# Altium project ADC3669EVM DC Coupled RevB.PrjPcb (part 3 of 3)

## Sheet FTDI USB Input.SchDoc: FTDI USB
size 431 x 279 mm; Date: Not shown in title block; ApprovedBy: Not shown in title block; CheckedBy: Not shown in title block; Author: Not shown in title block; CompanyName: Not shown in title block; Engineer: Not shown in title block; Organization: Not shown in title block; Address1: Not shown in title block; Address2: Not shown in title block; Address3: Not shown in title block; Address4: Not shown in title block; DocumentNumber: 1; Revision: Use project parameter SCH_Rev; SheetNumber: 13; SheetTotal: 17; PageSetup: Record=PageOptions¦CenterHorizontal=True¦CenterVertical=True¦PrintScale=1.00¦XCorrection=1.00¦YCorrection=1.00¦PrintKind=0¦BorderSize=5000000¦LeftOffset=0¦BottomOffset=0¦Orientation=2¦PaperLength=1000¦PaperWidth=1000¦Scale=100¦PaperSource=15¦PrintQuality=600¦MediaType=1¦DitherType=10¦PaperKind=Letter¦PrintScaleMode=1
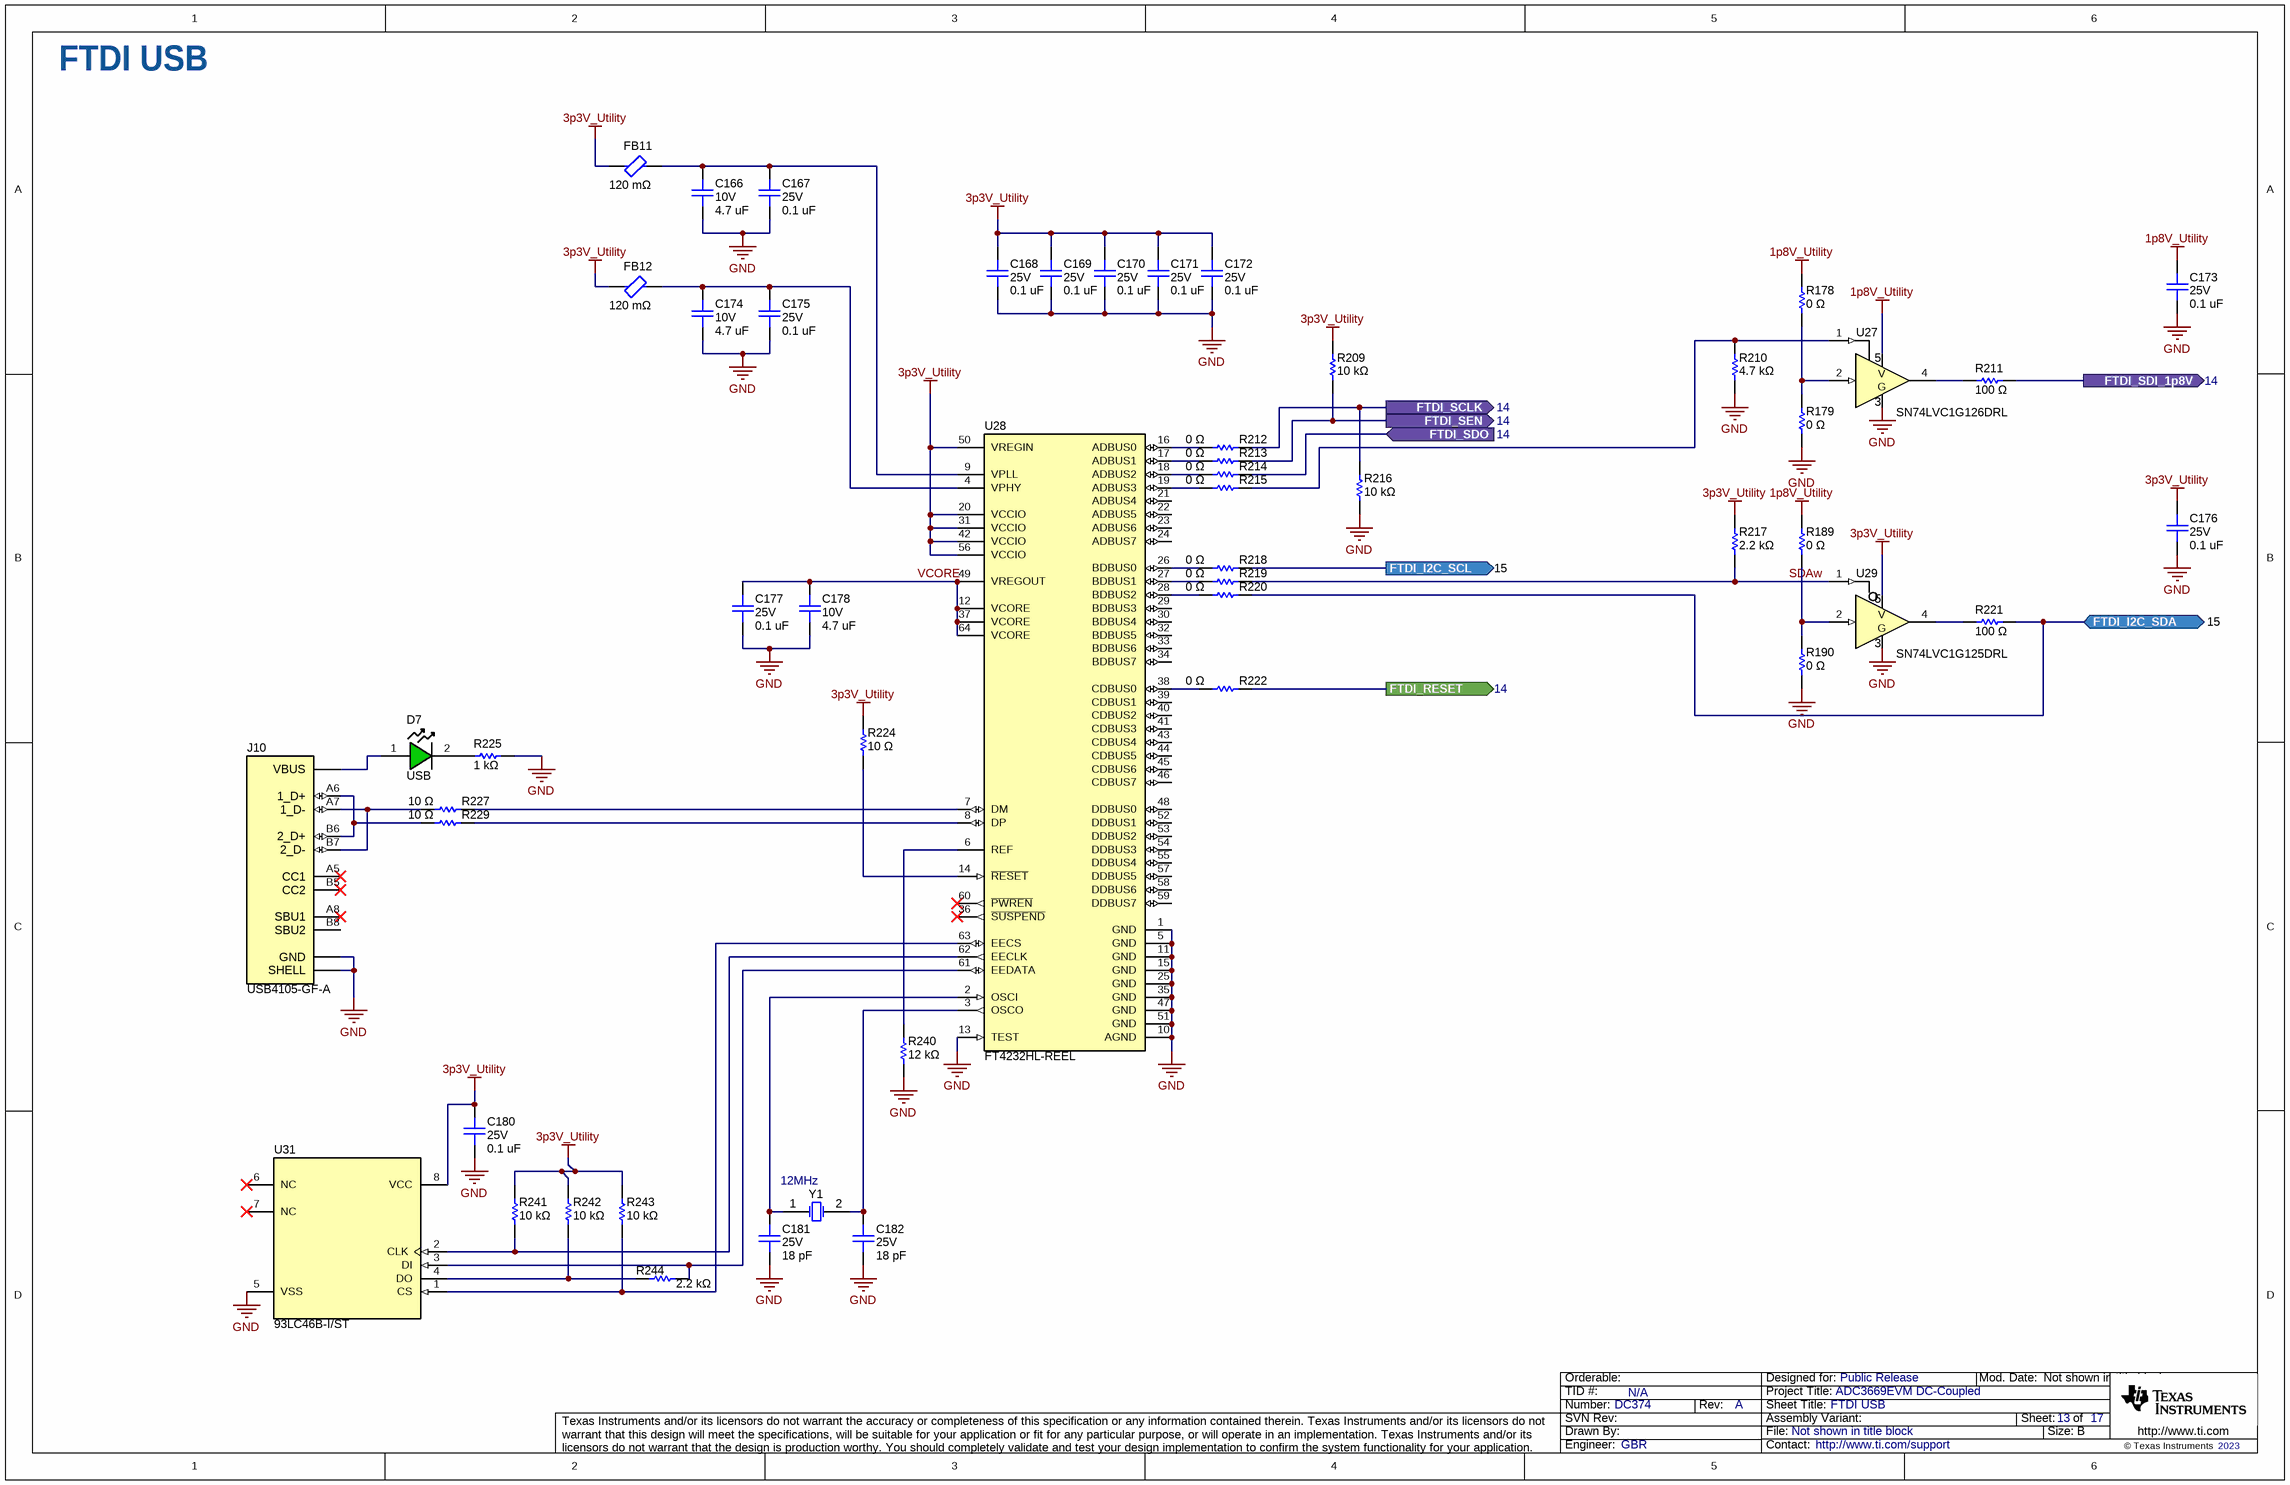
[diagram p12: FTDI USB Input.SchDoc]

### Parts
C166  value 4.7 uF  Voltage - Rated: 10V  [0402L_cap]  (hidden comment: C1005X5R1A475K050BE)
C167  value 0.1 uF  Voltage - Rated: 25V  [0402L_cap]  (hidden comment: C1005X5R1E104K050BC)
C168  value 0.1 uF  Voltage - Rated: 25V  [0402L_cap]  (hidden comment: C1005X5R1E104K050BC)
C169  value 0.1 uF  Voltage - Rated: 25V  [0402L_cap]  (hidden comment: C1005X5R1E104K050BC)
C170  value 0.1 uF  Voltage - Rated: 25V  [0402L_cap]  (hidden comment: C1005X5R1E104K050BC)
C171  value 0.1 uF  Voltage - Rated: 25V  [0402L_cap]  (hidden comment: C1005X5R1E104K050BC)
C172  value 0.1 uF  Voltage - Rated: 25V  [0402L_cap]  (hidden comment: C1005X5R1E104K050BC)
C173  value 0.1 uF  Voltage - Rated: 25V  [0402L_cap]  (hidden comment: C1005X5R1E104K050BC)
C174  value 4.7 uF  Voltage - Rated: 10V  [0402L_cap]  (hidden comment: C1005X5R1A475K050BE)
C175  value 0.1 uF  Voltage - Rated: 25V  [0402L_cap]  (hidden comment: C1005X5R1E104K050BC)
C176  value 0.1 uF  Voltage - Rated: 25V  [0402L_cap]  (hidden comment: C1005X5R1E104K050BC)
C177  value 0.1 uF  Voltage - Rated: 25V  [0402L_cap]  (hidden comment: C1005X5R1E104K050BC)
C178  value 4.7 uF  Voltage - Rated: 10V  [0402L_cap]  (hidden comment: C1005X5R1A475K050BE)
C180  value 0.1 uF  Voltage - Rated: 25V  [0402L_cap]  (hidden comment: C1005X5R1E104K050BC)
C181  value 18 pF  Voltage - Rated: 25V  [0201_cap]  (hidden comment: GJM0335C1E180GB01D)
C182  value 18 pF  Voltage - Rated: 25V  [0201_cap]  (hidden comment: GJM0335C1E180GB01D)
D7  Text1: USB  [LED_LTST-C190-Green]  (hidden comment: LTST-C191TGKT)
FB11  DCR: 120 mΩ  [0402L]  (hidden comment: NFZ15SG151SN11D)
FB12  DCR: 120 mΩ  [0402L]  (hidden comment: NFZ15SG151SN11D)
J10  USB4105-GF-A  [FP-USB4105-GF-A_CONN_USB_9MM58_7MM53-MFG]
R178  value 0 Ω  [0402L]  (hidden comment: ERJ-2GE0R00X)
R179  value 0 Ω  [0402L]  (hidden comment: ERJ-2GE0R00X)
R189  value 0 Ω  [0402L]  (hidden comment: ERJ-2GE0R00X)
R190  value 0 Ω  [0402L]  (hidden comment: ERJ-2GE0R00X)
R209  value 10 kΩ  [0402L]  (hidden comment: ERJ-2RKF1002X)
R210  value 4.7 kΩ  [0402L]  (hidden comment: ERJ-H2RF4701X)
R211  value 100 Ω  [0402L]  (hidden comment: ERJ-H2RF1000X)
R212  value 0 Ω  [0402L]  (hidden comment: ERJ-2GE0R00X)
R213  value 0 Ω  [0402L]  (hidden comment: ERJ-2GE0R00X)
R214  value 0 Ω  [0402L]  (hidden comment: ERJ-2GE0R00X)
R215  value 0 Ω  [0402L]  (hidden comment: ERJ-2GE0R00X)
R216  value 10 kΩ  [0402L]  (hidden comment: ERJ-2RKF1002X)
R217  value 2.2 kΩ  [0402L]  (hidden comment: ERJ-2RKF2201X)
R218  value 0 Ω  [0402L]  (hidden comment: ERJ-2GE0R00X)
R219  value 0 Ω  [0402L]  (hidden comment: ERJ-2GE0R00X)
R220  value 0 Ω  [0402L]  (hidden comment: ERJ-2GE0R00X)
R221  value 100 Ω  [0402L]  (hidden comment: ERJ-H2RF1000X)
R222  value 0 Ω  [0402L]  (hidden comment: ERJ-2GE0R00X)
R224  value 10 Ω  [0402L]  (hidden comment: ERJ-2RKF10R0X)
R225  value 1 kΩ  [0402L]  (hidden comment: ERJ-2RKF1001X)
R227  value 10 Ω  [0402L]  (hidden comment: ERJ-2RKF10R0X)
R229  value 10 Ω  [0402L]  (hidden comment: ERJ-2RKF10R0X)
R240  value 12 kΩ  [0402L]  (hidden comment: ERA-2ARB123X)
R241  value 10 kΩ  [0402L]  (hidden comment: ERJ-2RKF1002X)
R242  value 10 kΩ  [0402L]  (hidden comment: ERJ-2RKF1002X)
R243  value 10 kΩ  [0402L]  (hidden comment: ERJ-2RKF1002X)
R244  value 2.2 kΩ  [0402L]  (hidden comment: ERJ-2RKF2201X)
U27  SN74LVC1G126DRL  [DRL0005A]
U28  FT4232HL-REEL  [LQFP64-MFG]
U29  SN74LVC1G125DRL  [DRL0005A]
U31  93LC46B-I/ST  [TSSOP-8]
Y1  Text: 12MHz  [XTAL_ABM3]  (hidden comment: ABM3-12.000MHZ-D2Y-T)

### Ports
FTDI_I2C_SCL (out, see 15), FTDI_I2C_SDA (bidir, see 15), FTDI_RESET (out, see 14), FTDI_SCLK (out, see 14), FTDI_SDI_1p8V (out, see 14), FTDI_SDO (in, see 14), FTDI_SEN (out, see 14)

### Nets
1p8V_Utility: C173.2 R178.2 R189.2 U27.5(VCC)
3p3V_Utility: C168.2 C169.2 C170.2 C171.2 C172.2 C176.2 C180.2 FB11.1 FB12.1 R209.2 R217.2 R224.2 R241.2 R242.2 R243.2 U28.20(VCCIO) U28.31(VCCIO) U28.42(VCCIO) U28.50(VREGIN) U28.56(VCCIO) U29.5(VCC) U31.8(VCC)
GND: C166.1 C167.1 C168.1 C169.1 C170.1 C171.1 C172.1 C173.1 C174.1 C175.1 C176.1 C177.1 C178.1 C180.1 C181.1 C182.1 J10.1,2,3,4(SHELL) J10.A1,B1(GND) R179.1 R190.1 R210.1 R216.1 R225.1 R240.1 U27.3(GND) U28.1(GND) U28.5(GND) U28.10(AGND) U28.11(GND) U28.13(TEST) U28.15(GND) U28.25(GND) U28.35(GND) U28.47(GND) U28.51(GND) U29.3(GND) U31.5(VSS)
FTDI_I2C_SCL: R218.2 ; port FTDI_I2C_SCL
FTDI_I2C_SDA: R220.2 R221.2 ; port FTDI_I2C_SDA
FTDI_RESET: R222.2 ; port FTDI_RESET
FTDI_SCLK: R212.2 R216.2 ; port FTDI_SCLK
FTDI_SDI_1p8V: R211.2 ; port FTDI_SDI_1p8V
FTDI_SDO: R214.2 ; port FTDI_SDO
FTDI_SEN: R209.1 R213.2 ; port FTDI_SEN
SDAw: R217.1 R219.2 U29.1(~{OE})
VCORE: C177.2 C178.2 U28.12(VCORE) U28.37(VCORE) U28.49(VREGOUT) U28.64(VCORE)
NetC166_2: C166.2 C167.2 FB11.2 U28.9(VPLL)
NetC174_2: C174.2 C175.2 FB12.2 U28.4(VPHY)
NetC181_2: C181.2 U28.2(OSCI) Y1.1(OSC1)
NetC182_2: C182.2 U28.3(OSCO) Y1.2(OSC2)
NetD7_1: D7.1(A) J10.A4,B4(VBUS)
NetD7_2: D7.2(K) R225.2
NetJ10_A6: J10.A6(1_D+) J10.B6(2_D+) R229.1
NetJ10_A7: J10.A7(1_D-) J10.B7(2_D-) R227.1
NetR178_1: R178.1 R179.2 U27.2(A)
NetR189_1: R189.1 R190.2 U29.2(A)
NetR210_2: R210.2 R215.2 U27.1(~{OE})
NetR211_1: R211.1 U27.4(Y)
NetR212_1: R212.1 U28.16(ADBUS0)
NetR213_1: R213.1 U28.17(ADBUS1)
NetR214_1: R214.1 U28.18(ADBUS2)
NetR215_1: R215.1 U28.19(ADBUS3)
NetR218_1: R218.1 U28.26(BDBUS0)
NetR219_1: R219.1 U28.27(BDBUS1)
NetR220_1: R220.1 U28.28(BDBUS2)
NetR221_1: R221.1 U29.4(Y)
NetR222_1: R222.1 U28.38(CDBUS0)
NetR224_1: R224.1 U28.14(~{RESET})
NetR227_2: R227.2 U28.7(DM)
NetR229_2: R229.2 U28.8(DP)
NetR240_2: R240.2 U28.6(REF)
NetR241_1: R241.1 U28.62(EECLK) U31.2(CLK)
NetR242_1: R242.1 R244.1 U31.4(DO)
NetR243_1: R243.1 U28.63(EECS) U31.1(CS)
NetR244_2: R244.2 U28.61(EEDATA) U31.3(DI)

Not connected (* = marked no-connect by the designer): J10 A5(CC1)* A8(SBU1)* B5(CC2)* B8(SBU2); U28 21(ADBUS4) 22(ADBUS5) 23(ADBUS6) 24(ADBUS7) 29(BDBUS3) 30(BDBUS4) 32(BDBUS5) 33(BDBUS6) 34(BDBUS7) 36(~{SUSPEND})* 39(CDBUS1) 40(CDBUS2) 41(CDBUS3) 43(CDBUS4) 44(CDBUS5) 45(CDBUS6) 46(CDBUS7) 48(DDBUS0) 52(DDBUS1) 53(DDBUS2) 54(DDBUS3) 55(DDBUS4) 57(DDBUS5) 58(DDBUS6) 59(DDBUS7) 60(~{PWREN})*; U31 6(NC)* 7(NC)*

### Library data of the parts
C166 C174 C178 = capcc03139: CAP CER 4.7UF 10V X5R 0402; Manufacturer: TDK Corporation; CompType: Capacitor Ceramic; Tolerance: ±10%; SizeX_mm: 1; SizeY_mm: 0.5; SizeZ_mm: 0.7
C167-C173 C175-C177 C180 = capcc01263: CAP CER 0.1UF 25V X5R 0402; Manufacturer: TDK Corporation; CompType: Capacitor Ceramic; Tolerance: ±10%; SizeX_mm: 1; SizeY_mm: 0.5; SizeZ_mm: 0.55
C181 C182 = capcc08351: CAP CER 18PF 25V C0G/NP0 0201; Manufacturer: Murata Electronics; CompType: Capacitor Ceramic; Tolerance: ±2%; Temperature Coefficient: C0G, NP0; SizeX_mm: 0.6; SizeY_mm: 0.3; SizeZ_mm: 0.33
D7 = cmp00247: LED GREEN CLEAR CHIP SMD; Manufacturer: Lite-On Inc.; Current Rating (Amps): 20mA; Voltage - Forward (Vf) (Typ): 3.2V; SizeX_mm: 1.6; SizeY_mm: 0.8; SizeZ_mm: 0.65
FB11 FB12 = dcp00209: 0402 (1005) 150OHM (TYP.) 1000MA; Manufacturer: Murata Electronics; CompType: FerriteBead; Current: 1A
J10 = USB4105-GF-A: USB - C (Type - C) USB 2.0 Receptacle Connector 24 Position Surface Mount, Right Angle; Through Hole; Manufacturer: GCT; CompType: USB C
R178 R179 R189 R190 R212-R215 R218-R220 R222 = RSMD040200001: RES SMD 0 OHM JUMPER 1/10W 0402; Manufacturer: Panasonic Electronic Components; CompType: Resistor SMD; Power (Watts): 0.1W, 1/10W; SizeX_mm: 1; SizeY_mm: 0.5; SizeZ_mm: 0.4
R209 R216 R241-R243 = RSMD040200314: RES SMD 10K OHM 1% 1/10W 0402; Manufacturer: Panasonic Electronic Components; CompType: Resistor SMD; Power (Watts): 0.1W, 1/10W; Temperature Coefficient: ±100ppm/°C; SizeX_mm: 1; SizeY_mm: 0.5; SizeZ_mm: 0.4
R210 = RSMD040202592: RES 4.7K OHM 1% 1/10W 0402; Manufacturer: Panasonic Electronic Components; CompType: Resistor SMD; Power (Watts): 0.1W, 1/10W; Temperature Coefficient: ±100ppm/°C; SizeX_mm: 1; SizeY_mm: 0.5; SizeZ_mm: 0.4
R211 R221 = RSMD040200378: RES 100 OHM 1% 1/10W 0402; Manufacturer: Panasonic Electronic Components; CompType: Resistor SMD; Power (Watts): 0.1W, 1/10W; Temperature Coefficient: ±100ppm/°C; SizeX_mm: 1; SizeY_mm: 0.5; SizeZ_mm: 0.4
R217 R244 = RSMD040201203: RES SMD 2.2K OHM 1% 1/10W 0402; Manufacturer: Panasonic Electronic Components; CompType: Resistor SMD; Power (Watts): 0.1W, 1/10W; Temperature Coefficient: ±100ppm/°C; SizeX_mm: 1; SizeY_mm: 0.5; SizeZ_mm: 0.4
R224 R227 R229 = RSMD040200331: RES SMD 10 OHM 1% 1/10W 0402; Manufacturer: Panasonic Electronic Components; CompType: Resistor SMD; Power (Watts): 0.1W, 1/10W; Temperature Coefficient: ±100ppm/°C; SizeX_mm: 1; SizeY_mm: 0.5; SizeZ_mm: 0.4
R225 = RSMD040200006: RES SMD 1K OHM 1% 1/10W 0402; Manufacturer: Panasonic Electronic Components; CompType: Resistor SMD; Power (Watts): 0.1W, 1/10W; Temperature Coefficient: ±100ppm/°C; SizeX_mm: 1; SizeY_mm: 0.5; SizeZ_mm: 0.4
R240 = RSMD040200520: RES SMD 12K OHM 0.1% 1/16W 0402; Manufacturer: Panasonic Electronic Components; CompType: Resistor SMD; Power (Watts): 0.063W, 1/16W; Temperature Coefficient: ±10ppm/°C; SizeX_mm: 1; SizeY_mm: 0.5; SizeZ_mm: 0.4
U27 = SN74LVC1G126DRL: Single Bus Buffer Gate With 3-State Outputs. Active high enable.; Manufacturer: Texas Instruments
U28 = cmp00204: USB Interface IC USB HS to Quad UART/ SPI/JTAG/I2C LQFP-6; Manufacturer: FTDI; Alt PartNumber: FT4232HL-TRAY; Symbol Name: SYM-FT4232HL-REEL; CompType: uC
U29 = SN74LVC1G125DRL: Single Bus Buffer Gate With 3-State Outputs. Active low enable.; Manufacturer: Texas Instruments
U31 = cmp00156: 1K Microwire Compatible Serial EEPROM; Manufacturer: Microchip Technology; SymbolCreator: Altium; SizeArea_mm2: 19.2; SizeAreaWB_mm2: 42
Y1 = cmp00323: Crystal, 12 MHz, 18 pF, SMD; Manufacturer: Abracon Corporation; Frequency Stability: +/-30ppm; TaMax_C: 85°C; TaMin_C: -40°C

## Sheet Comms Level Shift.SchDoc
size 431 x 279 mm; Date: Not shown in title block; ApprovedBy: Not shown in title block; CheckedBy: Not shown in title block; Author: Not shown in title block; CompanyName: Not shown in title block; Engineer: Not shown in title block; Organization: Not shown in title block; Address1: Not shown in title block; Address2: Not shown in title block; Address3: Not shown in title block; Address4: Not shown in title block; DocumentNumber: 1; Revision: Use project parameter SCH_Rev; SheetNumber: 14; SheetTotal: 17; PageSetup: Record=PageOptions¦CenterHorizontal=True¦CenterVertical=True¦PrintScale=1.00¦XCorrection=1.00¦YCorrection=1.00¦PrintKind=0¦BorderSize=5000000¦LeftOffset=0¦BottomOffset=0¦Orientation=2¦PaperLength=1000¦PaperWidth=1000¦Scale=100¦PaperSource=15¦PrintQuality=600¦MediaType=1¦DitherType=10¦PaperKind=Letter¦PrintScaleMode=1
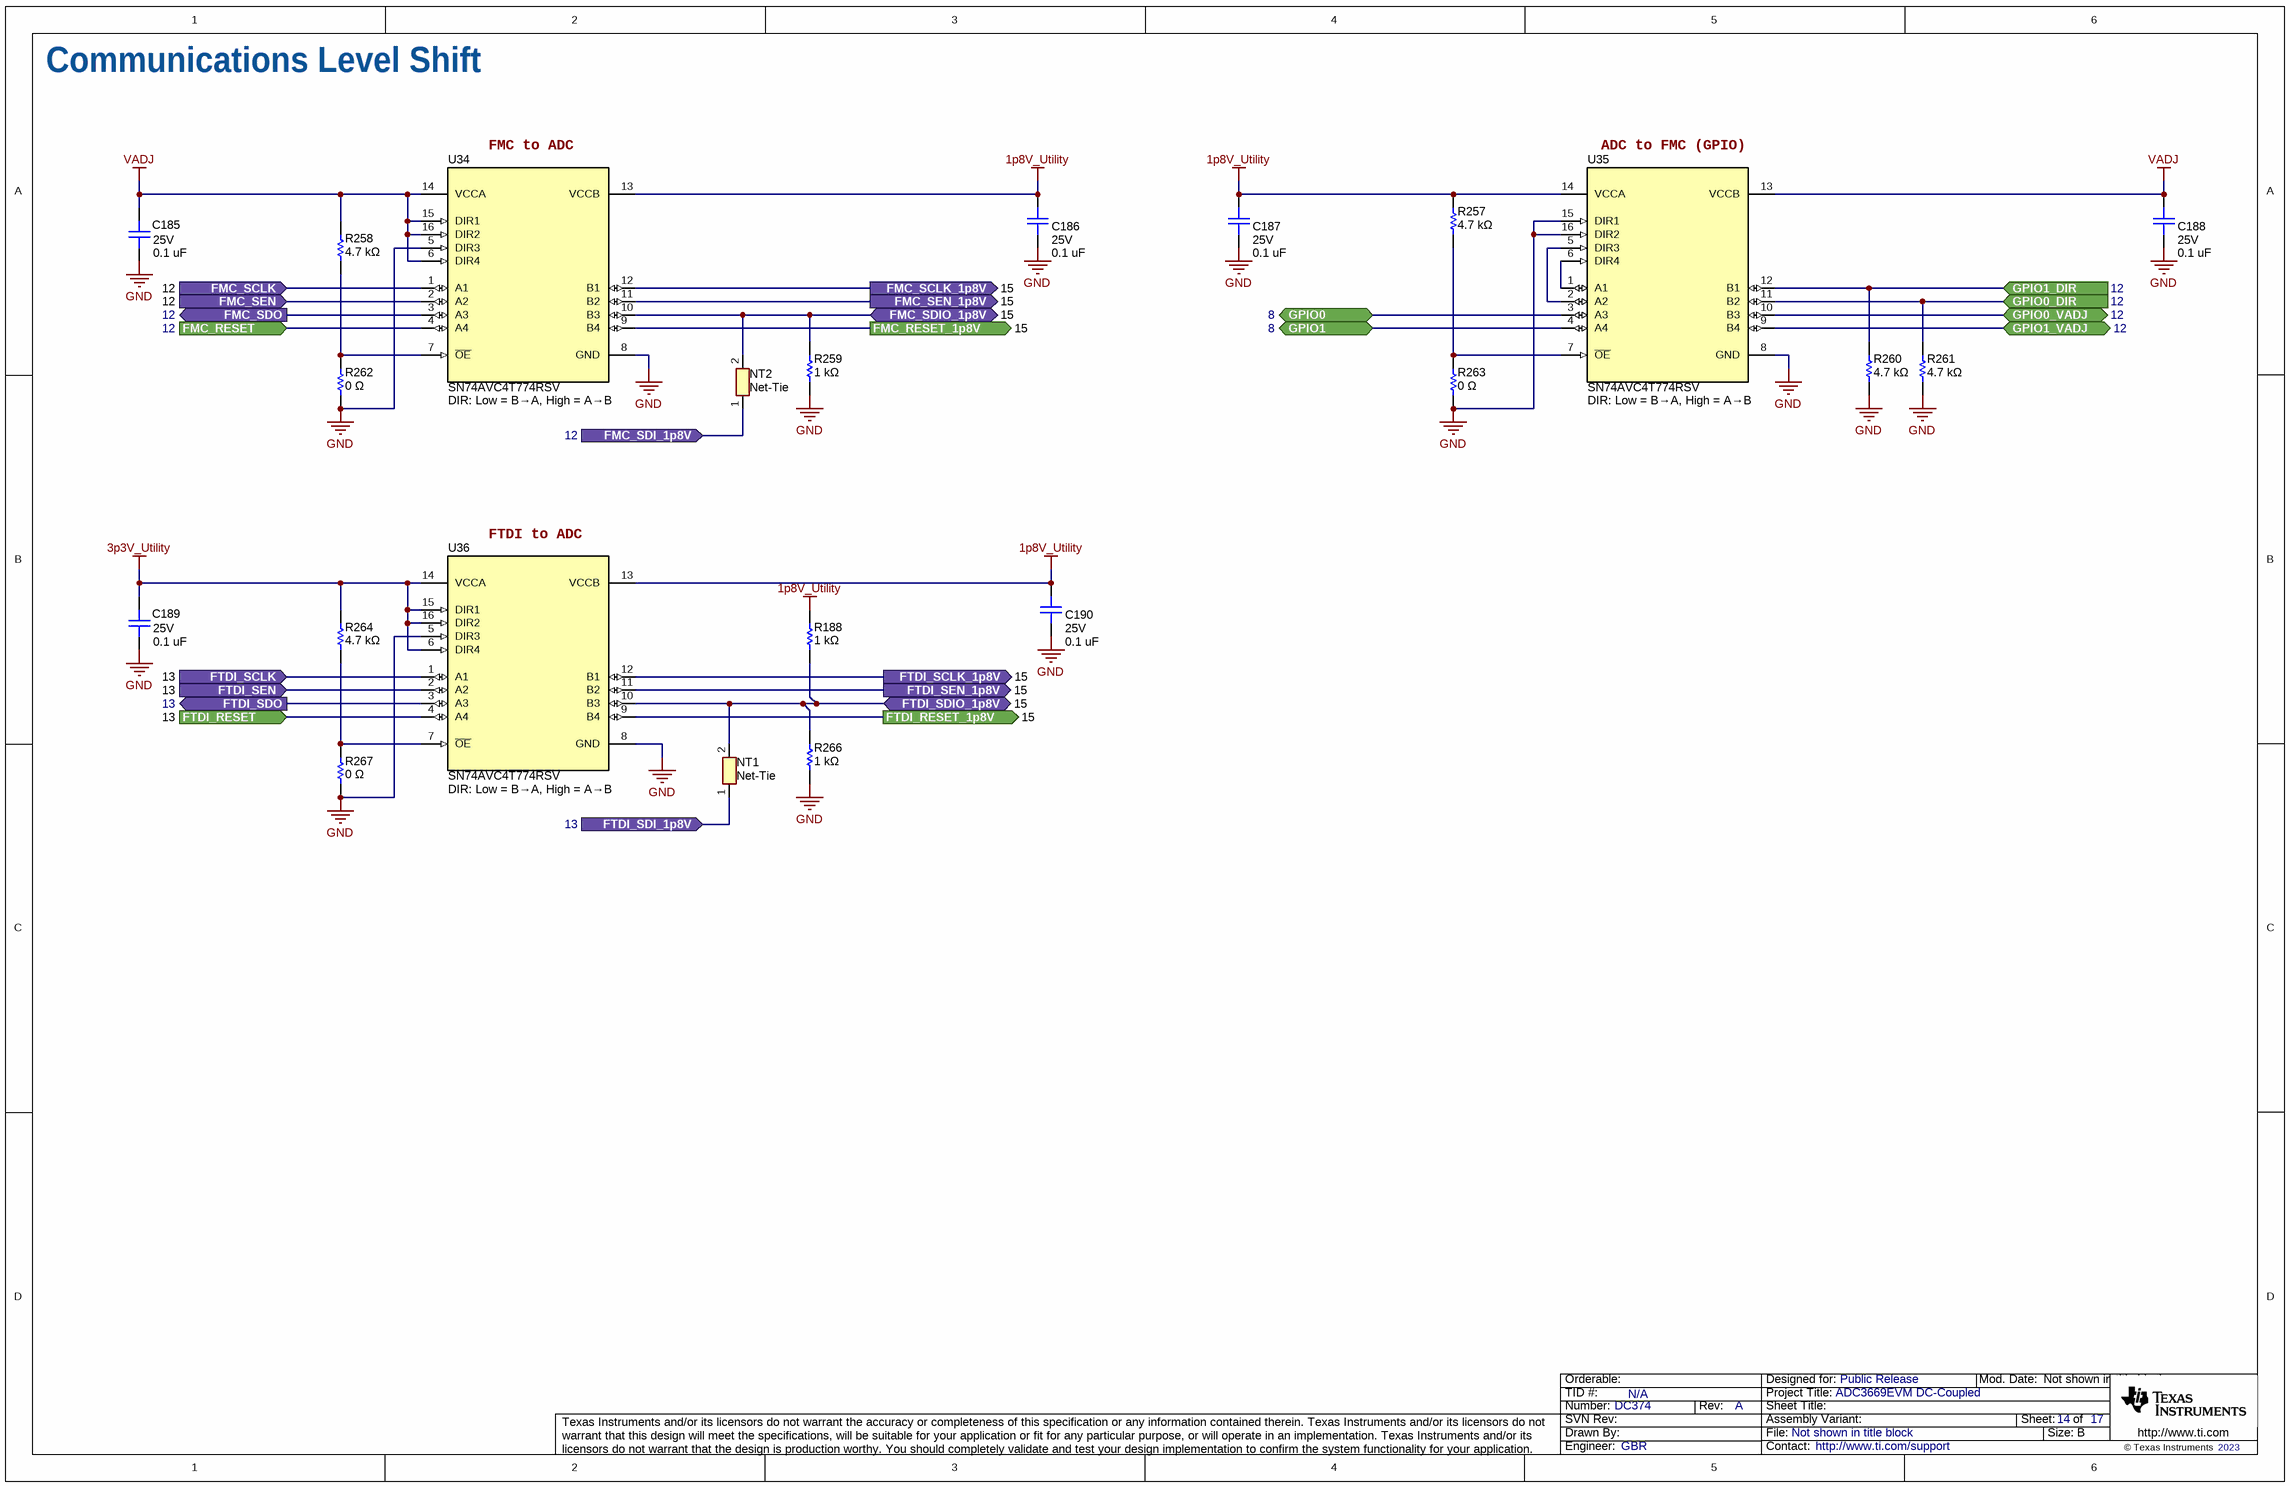
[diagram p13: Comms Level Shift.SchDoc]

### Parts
C185  value 0.1 uF  Voltage - Rated: 25V  [0402L_cap]  (hidden comment: C1005X5R1E104K050BC)
C186  value 0.1 uF  Voltage - Rated: 25V  [0402L_cap]  (hidden comment: C1005X5R1E104K050BC)
C187  value 0.1 uF  Voltage - Rated: 25V  [0402L_cap]  (hidden comment: C1005X5R1E104K050BC)
C188  value 0.1 uF  Voltage - Rated: 25V  [0402L_cap]  (hidden comment: C1005X5R1E104K050BC)
C189  value 0.1 uF  Voltage - Rated: 25V  [0402L_cap]  (hidden comment: C1005X5R1E104K050BC)
C190  value 0.1 uF  Voltage - Rated: 25V  [0402L_cap]  (hidden comment: C1005X5R1E104K050BC)
NT1  Net-Tie  [Net-Tie_5milWide_60milLong]  (net tie, no BOM)
NT2  Net-Tie  [Net-Tie_5milWide_60milLong]  (net tie, no BOM)
R188  value 1 kΩ  [0402L]  (hidden comment: ERA-2AED102X)
R257  value 4.7 kΩ  [0402L]  (hidden comment: ERJ-H2RF4701X)
R258  value 4.7 kΩ  [0402L]  (hidden comment: ERJ-2GEJ472X)
R259  value 1 kΩ  [0402L]  (hidden comment: ERA-2AED102X)
R260  value 4.7 kΩ  [0402L]  (hidden comment: ERJ-H2RF4701X)
R261  value 4.7 kΩ  [0402L]  (hidden comment: ERJ-H2RF4701X)
R262  value 0 Ω  [0402L]  (hidden comment: ERJ-2GE0R00X)
R263  value 0 Ω  [0402L]  (hidden comment: ERJ-2GE0R00X)
R264  value 4.7 kΩ  [0402L]  (hidden comment: ERJ-2GEJ472X)
R266  value 1 kΩ  [0402L]  (hidden comment: ERA-2AED102X)
R267  value 0 Ω  [0402L]  (hidden comment: ERJ-2GE0R00X)
U34  SN74AVC4T774RSV  Text1: DIR: Low = B→A, High = A→B  [RSV0016A]
U35  SN74AVC4T774RSV  Text1: DIR: Low = B→A, High = A→B  [RSV0016A]
U36  SN74AVC4T774RSV  Text1: DIR: Low = B→A, High = A→B  [RSV0016A]

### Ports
FMC_RESET (in, see 12), FMC_RESET_1p8V (out, see 15), FMC_SCLK (in, see 12), FMC_SCLK_1p8V (out, see 15), FMC_SDI_1p8V (in, see 12), FMC_SDIO_1p8V (bidir, see 15), FMC_SDO (out, see 12), FMC_SEN (in, see 12), FMC_SEN_1p8V (out, see 15), FTDI_RESET (in, see 13), FTDI_RESET_1p8V (out, see 15), FTDI_SCLK (in, see 13), FTDI_SCLK_1p8V (out, see 15), FTDI_SDI_1p8V (in, see 13), FTDI_SDIO_1p8V (bidir, see 15), FTDI_SDO (out, see 13), FTDI_SEN (in, see 13), FTDI_SEN_1p8V (out, see 15), GPIO0 (bidir, see 8), GPIO0_DIR (in, see 12), GPIO0_VADJ (bidir, see 12), GPIO1 (bidir, see 8), GPIO1_DIR (in, see 12), GPIO1_VADJ (bidir, see 12)

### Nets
1p8V_Utility: C186.1 C187.1 C190.1 R188.1 R257.2 U34.13(VCCB) U35.14(VCCA) U36.13(VCCB)
3p3V_Utility: C189.2 R264.2 U36.6(DIR4) U36.14(VCCA) U36.15(DIR1) U36.16(DIR2)
GND: C185.1 C186.2 C187.2 C188.2 C189.1 C190.2 R259.2 R260.1 R261.1 R262.1 R263.1 R266.2 R267.1 U34.5(DIR3) U34.8(GND) U35.8(GND) U35.15(DIR1) U35.16(DIR2) U36.5(DIR3) U36.8(GND)
VADJ: C185.2 C188.1 R258.2 U34.6(DIR4) U34.14(VCCA) U34.15(DIR1) U34.16(DIR2) U35.13(VCCB)
FMC_RESET: U34.4(A4) ; port FMC_RESET
FMC_RESET_1p8V: U34.9(B4) ; port FMC_RESET_1p8V
FMC_SCLK: U34.1(A1) ; port FMC_SCLK
FMC_SCLK_1p8V: U34.12(B1) ; port FMC_SCLK_1p8V
FMC_SDI_1p8V: NT2.1 ; port FMC_SDI_1p8V
FMC_SDIO_1p8V: NT2.2 R259.1 U34.10(B3) ; port FMC_SDIO_1p8V
FMC_SDO: U34.3(A3) ; port FMC_SDO
FMC_SEN: U34.2(A2) ; port FMC_SEN
FMC_SEN_1p8V: U34.11(B2) ; port FMC_SEN_1p8V
FTDI_RESET: U36.4(A4) ; port FTDI_RESET
FTDI_RESET_1p8V: U36.9(B4) ; port FTDI_RESET_1p8V
FTDI_SCLK: U36.1(A1) ; port FTDI_SCLK
FTDI_SCLK_1p8V: U36.12(B1) ; port FTDI_SCLK_1p8V
FTDI_SDI_1p8V: NT1.1 ; port FTDI_SDI_1p8V
FTDI_SDIO_1p8V: NT1.2 R188.2 R266.1 U36.10(B3) ; port FTDI_SDIO_1p8V
FTDI_SDO: U36.3(A3) ; port FTDI_SDO
FTDI_SEN: U36.2(A2) ; port FTDI_SEN
FTDI_SEN_1p8V: U36.11(B2) ; port FTDI_SEN_1p8V
GPIO0: U35.3(A3) ; port GPIO0
GPIO0_DIR: R261.2 U35.11(B2) ; port GPIO0_DIR
GPIO0_VADJ: U35.10(B3) ; port GPIO0_VADJ
GPIO1: U35.4(A4) ; port GPIO1
GPIO1_DIR: R260.2 U35.12(B1) ; port GPIO1_DIR
GPIO1_VADJ: U35.9(B4) ; port GPIO1_VADJ
NetR257_1: R257.1 R263.2 U35.7(~{OE})
NetR258_1: R258.1 R262.2 U34.7(~{OE})
NetR264_1: R264.1 R267.2 U36.7(~{OE})
NetU35_1: U35.1(A1) U35.6(DIR4)
NetU35_2: U35.2(A2) U35.5(DIR3)

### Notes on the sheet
- Communications Level Shift
- Labels drawn without touching a wire or pin: ADC to FMC (GPIO), FMC to ADC, FTDI to ADC

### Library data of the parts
C185-C190 = capcc01263: CAP CER 0.1UF 25V X5R 0402; Manufacturer: TDK Corporation; SizeZ_mm: 0.55; SizeX_mm: 1; SizeY_mm: 0.5; CompType: Capacitor Ceramic; Tolerance: ±10%
NT1 NT2 = cmp00320: Single Point net tie; SymbolCreator: codlsc; CompType: NetTie
R188 R259 R266 = RSMD040200005: RES SMD 1K OHM 0.5% 1/16W 0402; Manufacturer: Panasonic Electronic Components; CompType: Resistor SMD; Power (Watts): 0.063W, 1/16W; Temperature Coefficient: ±25ppm/°C; SizeX_mm: 1; SizeY_mm: 0.5; SizeZ_mm: 0.4
R257 R260 R261 = RSMD040202592: as R210 on sheet FTDI USB Input
R258 R264 = RSMD040202585: RES SMD 4.7K OHM 5% 1/10W 0402; Manufacturer: Panasonic Electronic Components; CompType: Resistor SMD; Power (Watts): 0.1W, 1/10W; Temperature Coefficient: ±200ppm/°C; SizeX_mm: 1; SizeY_mm: 0.5; SizeZ_mm: 0.4
R262 R263 R267 = RSMD040200001: as R178 on sheet FTDI USB Input
U34-U36 = cmp00171: Translation - Voltage Levels 4-bit dual-supply bus transceiver with 3-state outputs and independent direction control inputs; Manufacturer: Texas Instruments; Alt PartNumber: SN74AXC4T774RSV; CompType: Level Shifter

## Sheet I2C SPI Mux.SchDoc
size 431 x 279 mm; Date: Not shown in title block; ApprovedBy: Not shown in title block; CheckedBy: Not shown in title block; Author: Not shown in title block; CompanyName: Not shown in title block; Engineer: Not shown in title block; Organization: Not shown in title block; Address1: Not shown in title block; Address2: Not shown in title block; Address3: Not shown in title block; Address4: Not shown in title block; DocumentNumber: 1; Revision: Use project parameter SCH_Rev; SheetNumber: 15; SheetTotal: 17; PageSetup: Record=PageOptions¦CenterHorizontal=True¦CenterVertical=True¦PrintScale=1.00¦XCorrection=1.00¦YCorrection=1.00¦PrintKind=0¦BorderSize=5000000¦LeftOffset=0¦BottomOffset=0¦Orientation=2¦PaperLength=1000¦PaperWidth=1000¦Scale=100¦PaperSource=15¦PrintQuality=600¦MediaType=1¦DitherType=10¦PaperKind=Letter¦PrintScaleMode=1
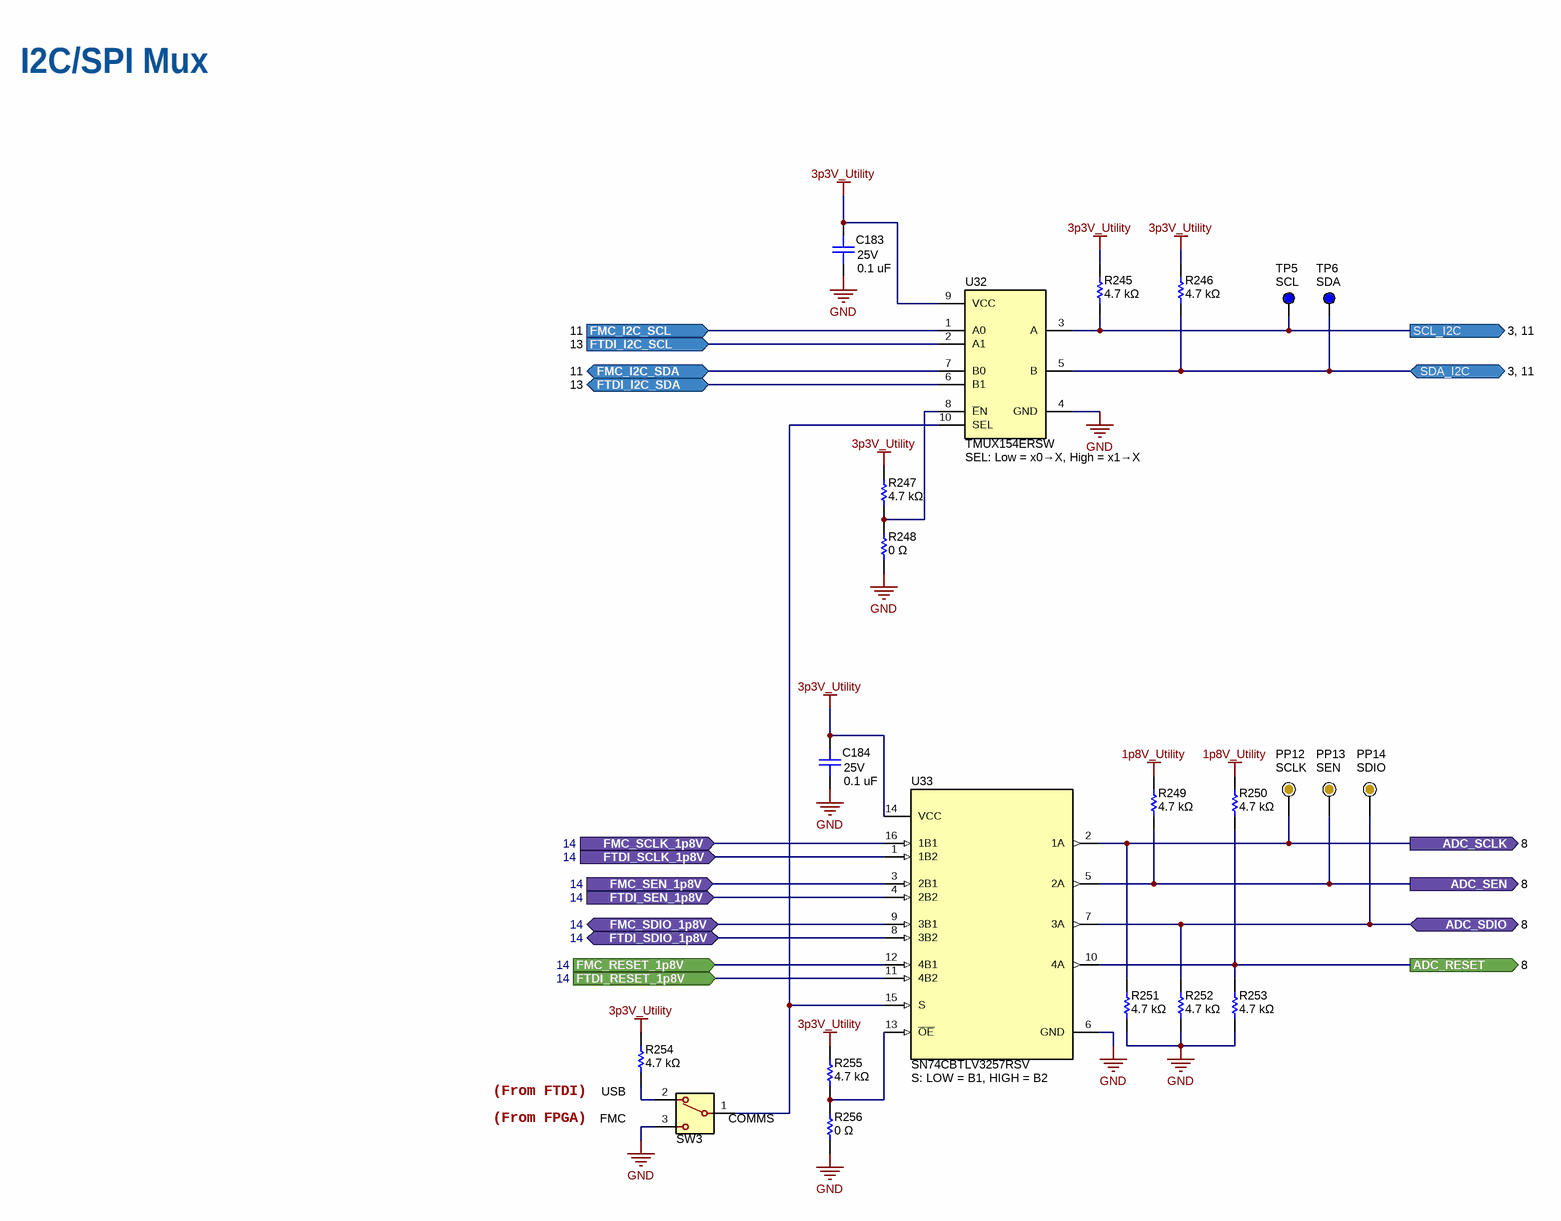
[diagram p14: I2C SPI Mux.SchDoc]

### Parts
C183  value 0.1 uF  Voltage - Rated: 25V  [0402L_cap]  (hidden comment: C1005X5R1E104K050BC)
C184  value 0.1 uF  Voltage - Rated: 25V  [0402L_cap]  (hidden comment: C1005X5R1E104K050BC)
PP12  Text1: SCLK  [ProbePoint_TH_40mil]  (hidden comment: Probe Point)  (no BOM)
PP13  Text1: SEN  [ProbePoint_TH_40mil]  (hidden comment: Probe Point)  (no BOM)
PP14  Text1: SDIO  [ProbePoint_TH_40mil]  (hidden comment: Probe Point)  (no BOM)
R245  value 4.7 kΩ  [0402L]  (hidden comment: ERJ-H2RF4701X)
R246  value 4.7 kΩ  [0402L]  (hidden comment: ERJ-H2RF4701X)
R247  value 4.7 kΩ  [0402L]  (hidden comment: ERJ-2GEJ472X)
R248  value 0 Ω  [0402L]  (hidden comment: ERJ-2GE0R00X)
R249  value 4.7 kΩ  [0402L]  (hidden comment: ERJ-H2RF4701X)
R250  value 4.7 kΩ  [0402L]  (hidden comment: ERJ-H2RF4701X)
R251  value 4.7 kΩ  [0402L]  (hidden comment: ERJ-H2RF4701X)
R252  value 4.7 kΩ  [0402L]  (hidden comment: ERJ-H2RF4701X)
R253  value 4.7 kΩ  [0402L]  (hidden comment: ERJ-H2RF4701X)
R254  value 4.7 kΩ  [0402L]  (hidden comment: ERJ-H2RF4701X)
R255  value 4.7 kΩ  [0402L]  (hidden comment: ERJ-2GEJ472X)
R256  value 0 Ω  [0402L]  (hidden comment: ERJ-2GE0R00X)
SW3  Text1: COMMS  Text2: USB  Text3: FMC  [450301014042]  (hidden comment: 450301014042)
TP5  Text1: SCL  [Keystone5117]  (hidden comment: cmp00058)
TP6  Text1: SDA  [Keystone5117]  (hidden comment: cmp00058)
U32  TMUX154ERSW  Text1: SEL: Low = x0→X, High = x1→X  [RSW0010A]
U33  SN74CBTLV3257RSV  Text1: S: LOW = B1, HIGH = B2  [RSV0016A]

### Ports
ADC_RESET (out, see 8), ADC_SCLK (out, see 8), ADC_SDIO (bidir, see 8), ADC_SEN (out, see 8), FMC_I2C_SCL (in, see 11), FMC_I2C_SDA (bidir, see 11), FMC_RESET_1p8V (in, see 14), FMC_SCLK_1p8V (in, see 14), FMC_SDIO_1p8V (bidir, see 14), FMC_SEN_1p8V (in, see 14), FTDI_I2C_SCL (in, see 13), FTDI_I2C_SDA (bidir, see 13), FTDI_RESET_1p8V (in, see 14), FTDI_SCLK_1p8V (in, see 14), FTDI_SDIO_1p8V (bidir, see 14), FTDI_SEN_1p8V (in, see 14), SCL_I2C (out, see 3, 11), SDA_I2C (bidir, see 3, 11)

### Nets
1p8V_Utility: R249.2 R250.2
3p3V_Utility: C183.2 C184.2 R245.2 R246.2 R247.2 R254.2 R255.2 U32.9(VCC) U33.14(VCC)
GND: C183.1 C184.1 R248.1 R251.1 R252.1 R253.1 R256.1 SW3.3 U32.4(GND) U33.6(GND)
ADC_RESET: R250.1 R253.2 U33.10(4A) ; port ADC_RESET
ADC_SCLK: PP12.1 R251.2 U33.2(1A) ; port ADC_SCLK
ADC_SDIO: PP14.1 R252.2 U33.7(3A) ; port ADC_SDIO
ADC_SEN: PP13.1 R249.1 U33.5(2A) ; port ADC_SEN
FMC_I2C_SCL: U32.1(A0) ; port FMC_I2C_SCL
FMC_I2C_SDA: U32.7(B0) ; port FMC_I2C_SDA
FMC_RESET_1p8V: U33.12(4B1) ; port FMC_RESET_1p8V
FMC_SCLK_1p8V: U33.16(1B1) ; port FMC_SCLK_1p8V
FMC_SDIO_1p8V: U33.9(3B1) ; port FMC_SDIO_1p8V
FMC_SEN_1p8V: U33.3(2B1) ; port FMC_SEN_1p8V
FTDI_I2C_SCL: U32.2(A1) ; port FTDI_I2C_SCL
FTDI_I2C_SDA: U32.6(B1) ; port FTDI_I2C_SDA
FTDI_RESET_1p8V: U33.11(4B2) ; port FTDI_RESET_1p8V
FTDI_SCLK_1p8V: U33.1(1B2) ; port FTDI_SCLK_1p8V
FTDI_SDIO_1p8V: U33.8(3B2) ; port FTDI_SDIO_1p8V
FTDI_SEN_1p8V: U33.4(2B2) ; port FTDI_SEN_1p8V
SCL_I2C: R245.1 TP5.1 U32.3(A) ; port SCL_I2C
SDA_I2C: R246.1 TP6.1 U32.5(B) ; port SDA_I2C
NetR247_1: R247.1 R248.2 U32.8(~{E}N)
NetR254_1: R254.1 SW3.2(COMM)
NetR255_1: R255.1 R256.2 U33.13(~{OE})
NetSW3_1: SW3.1 U32.10(SEL) U33.15(S)

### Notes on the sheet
- I2C/SPI Mux
- (From FTDI)
- (From FPGA)

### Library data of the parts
C183 C184 = capcc01263: as C185 on sheet Comms Level Shift
PP12-PP14 = cmp00025: Probe Point that can be used in lue of a test point
R245 R246 R249-R254 = RSMD040202592: as R210 on sheet FTDI USB Input
R247 R255 = RSMD040202585: as R258 on sheet Comms Level Shift
R248 R256 = RSMD040200001: as R178 on sheet FTDI USB Input
SW3 = cmp00353: Switch Slide SPDT 12V, 500mA; Manufacturer: Wurth Elektronik
TP5 TP6 = cmp00058: Test Point, Miniature, Blue, TH; PartNumber: 5117; Manufacturer: Keystone
U32 = cmp00300: ESD-Protected, Low Capacitance, 2-Channel, 2:1 Switch, With Powered-off Protection; PartNumber: TMUX154ERSWR; Manufacturer: Texas Instruments; CompType: MUX
U33 = SN74CBTLV3257RSV: Low-Voltage 4-Bit 1-of-2 FET Multiplexer/Demultiplexe; PartNumber: SN74CBTLV3257RSVR; Manufacturer: Texas Instruments; UniqueID: cmp00269; CompType: MUX

## Sheet Hardware.SchDoc: Mechanicals
size 431 x 279 mm; Date: Not shown in title block; ApprovedBy: Not shown in title block; CheckedBy: Not shown in title block; Author: Not shown in title block; CompanyName: Not shown in title block; Engineer: Not shown in title block; Organization: Not shown in title block; Address1: Not shown in title block; Address2: Not shown in title block; Address3: Not shown in title block; Address4: Not shown in title block; DocumentNumber: 4; Revision: Use project parameter SCH_Rev; SheetNumber: 16; SheetTotal: 17; PageSetup: Record=PageOptions¦CenterHorizontal=True¦CenterVertical=True¦PrintScale=1.00¦XCorrection=1.00¦YCorrection=1.00¦PrintKind=0¦BorderSize=5000000¦LeftOffset=0¦BottomOffset=0¦Orientation=2¦PaperLength=1000¦PaperWidth=1000¦Scale=100¦PaperSource=15¦PrintQuality=600¦MediaType=1¦DitherType=10¦PaperKind=Letter¦PrintScaleMode=1
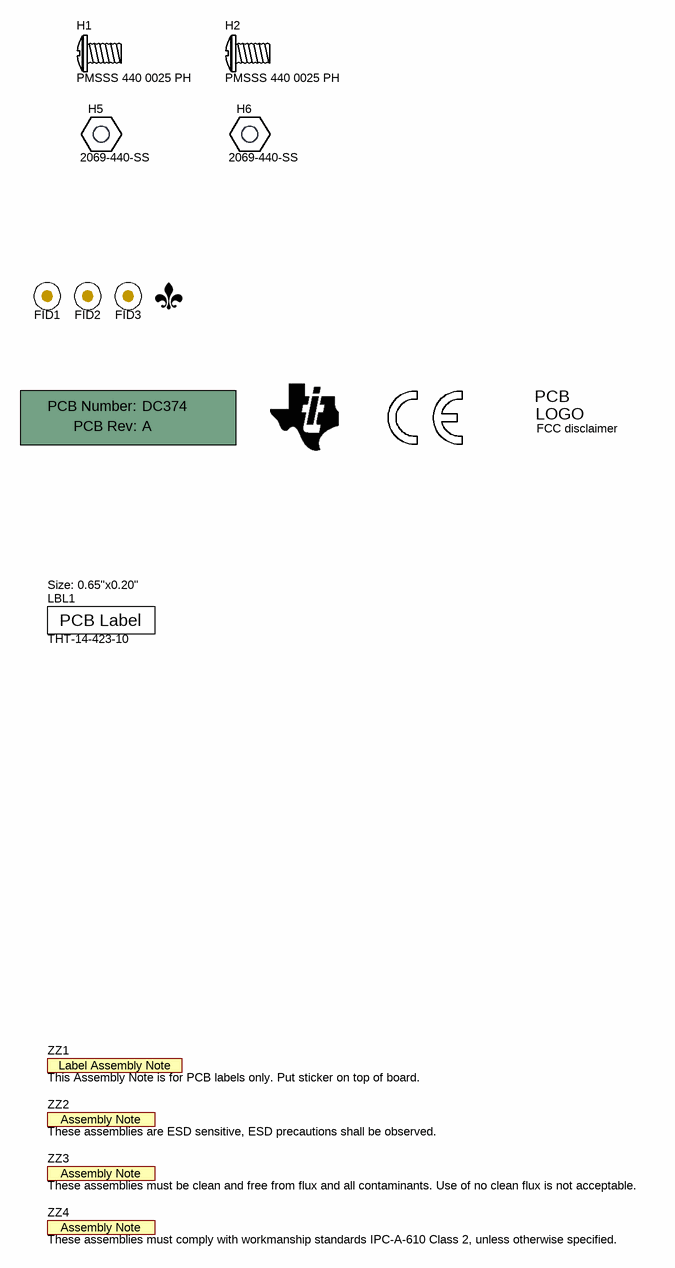
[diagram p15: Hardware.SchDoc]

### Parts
!PCB1  Printed Circuit Board  (value not drawn)  (mechanical)
FID1  Fiducial Mark  [Fiducial10-20]  (value not drawn)  (no BOM)
FID2  Fiducial Mark  [Fiducial10-20]  (value not drawn)  (no BOM)
FID3  Fiducial Mark  [Fiducial10-20]  (value not drawn)  (no BOM)
H1  PMSSS 440 0025 PH  [4400025PH]  (mechanical)
H2  PMSSS 440 0025 PH  [4400025PH]  (mechanical)
H5  2069-440-SS  [FP-2116-440-AL_STANDOFF_HEX_1-4-MFG]
H6  2069-440-SS  [FP-2116-440-AL_STANDOFF_HEX_1-4-MFG]
LBL1  THT-14-423-10  Text1: Size: 0.65"x0.20"  [Label_650x200]
Logo1  FDL Logo  [FDL_Small]  (value not drawn)  (no BOM)
Logo2  FCC disclaimer  [FCC_disclaimer_stacked]  (no BOM)
Logo3  ESD Overlay  [ESD_Overlay_Medium]  (value not drawn)  (no BOM)
Logo4  WEEE  [WEEE_Minimum]  (value not drawn)  (no BOM)
LOGO5  CE Mark  [CE_Mark_5mm]  (value not drawn)  (no BOM)
Logo6  Texas Instruments  [TI_Stacked_Overlay_Small]  (value not drawn)  (no BOM)
ZZ1  This Assembly Note is for PCB labels only. Put sticker on top of board.  [AssemblyNoteLabel]  (no BOM)
ZZ2  These assemblies are ESD sensitive, ESD precautions shall be observed.  [AssemblyNote]  (no BOM)
ZZ3  These assemblies must be clean and free from flux and all contaminants. Use of no clean flux is not acceptable.  [AssemblyNote]  (no BOM)
ZZ4  These assemblies must comply with workmanship standards IPC-A-610 Class 2, unless otherwise specified.  [AssemblyNote]  (no BOM)

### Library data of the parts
!PCB1 = cmp00109: CompType: PCB
FID1-FID3 = mech00005: Fiducial; SymbolCreator: a0412235
H1 H2 = cmp00095: MACHINE SCREW PAN PHILLIPS 4-40; Manufacturer: B&F Fastener Supply
H5 H6 = cmp00097: Hex Standoff Threaded #4-40 Stainless Steel 1.250" (31.75mm) 1 1/4; Manufacturer: RAF Electronic Hardware; Pitch (mm): 4-40
LBL1 = cmp00106: Thermal Transfer Printable Labels, 0.650" W x 0.200" H - 10,000 per roll; Manufacturer: Brady; CompType: Label
Logo1 = cmp00105: FDL
Logo2 = cmp00102: FCC_disclaimer; CompType: Logo
Logo3 = cmp00317: CompType: Logo
Logo4 = cmp00101: CompType: Logo
LOGO5 = cmp00103: CE_Mark; CompType: Logo
Logo6 = cmp00104: Texas Instrument Corporate Signature; PartNumber: TI Bug; CompType: Logo
ZZ1 = CMP-0003616-3: This Assembly Note is for PCB labels only
ZZ2 = CMP-0077236-1
ZZ3 = CMP-0077237-1
ZZ4 = CMP-0077238-1

## Sheet Revision History.SchDoc: Rev History & Variants
size 431 x 279 mm; Date: Not shown in title block; ApprovedBy: Not shown in title block; CheckedBy: Not shown in title block; Author: Not shown in title block; CompanyName: Not shown in title block; Engineer: Not shown in title block; Organization: Not shown in title block; Address1: Not shown in title block; Address2: Not shown in title block; Address3: Not shown in title block; Address4: Not shown in title block; DocumentNumber: 5; Revision: Use project parameter SCH_Rev; SheetNumber: 17; SheetTotal: 17; PageSetup: Record=PageOptions¦CenterHorizontal=True¦CenterVertical=True¦PrintScale=1.00¦XCorrection=1.00¦YCorrection=1.00¦PrintKind=0¦BorderSize=5000000¦LeftOffset=0¦BottomOffset=0¦Orientation=2¦PaperLength=1000¦PaperWidth=1000¦Scale=100¦PaperSource=15¦PrintQuality=600¦MediaType=1¦DitherType=10¦PaperKind=Letter¦PrintScaleMode=1
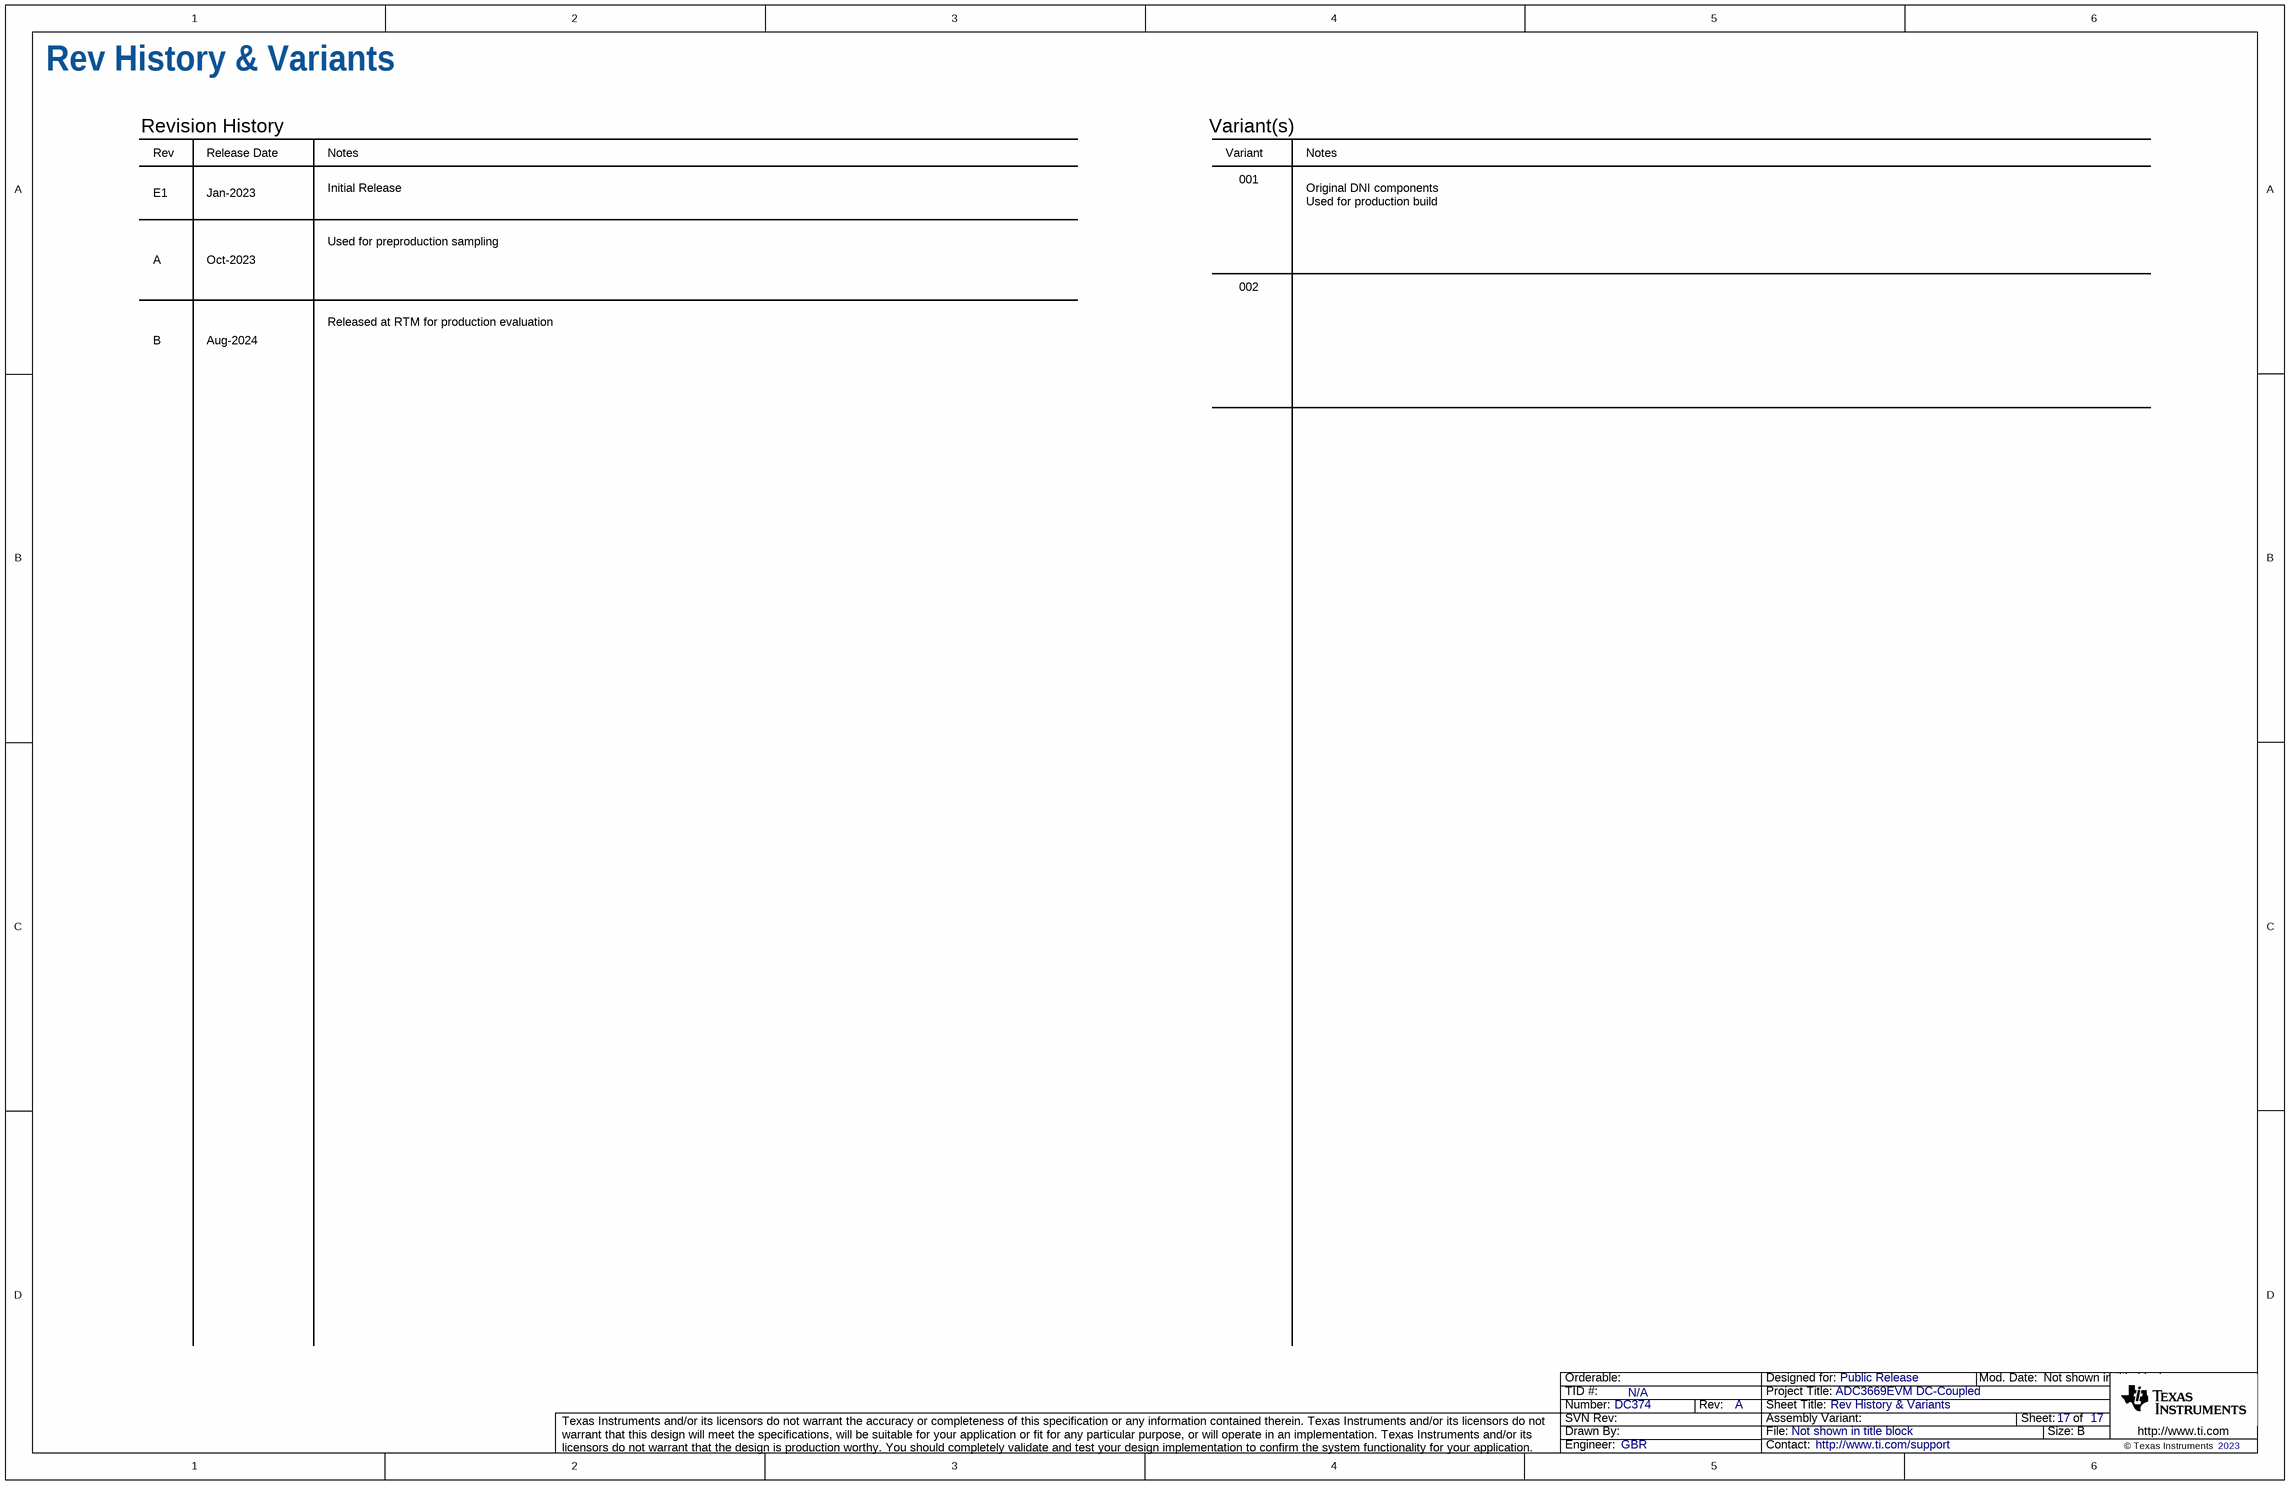
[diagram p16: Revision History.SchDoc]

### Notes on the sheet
- Rev
- Release Date
- Revision History
- Notes
- Variant
- Variant(s)
- E1
- Jan-2023
- Initial Release
- 001
- A
- Oct-2023
- Used for preproduction sampling
- 002
- Original DNI components
  Used for production build
- B
- Aug-2024
- Released at RTM for production evaluation

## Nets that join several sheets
1p8V_Utility: EVM Power (C9.2 R9.2 U4.1), ADC IO (6 pins), FMC Sections 8-14 (C165.2 R79.2 U26.5), FTDI USB Input (C173.2 R178.2 R189.2 U27.5), Comms Level Shift (8 pins), I2C SPI Mux (R249.2 R250.2)
2p3V_LDO: ADC Power DC-DC (5 pins), ADC Power (16 pins)
3p3V_Utility: EVM Power (21 pins), ADC Power DC-DC (R13.2 R273.2 R274.2 R275.2), ADC Power (16 pins), LMH Power DC-DC (R64.2 U45.6), FMC Sections 1-7  (D6.2), FTDI USB Input (22 pins), Comms Level Shift (6 pins), I2C SPI Mux (9 pins)
3p9V_LMH: LMH Power LDO (C77.2 C78.2 FC6.3), Amplifier (18 pins)
4p3V_LDO: LMH Power DC-DC (5 pins), LMH Power LDO (C50.2 C51.2 R73.2 U16.3)
12V_FMC: EVM Power (PP1.1 SW1.3), FMC Sections 1-7  (J9.C35 J9.C37)
-1p1V_LMH: LMH Power LDO (C71.2 C72.2 FC5.3), Amplifier (14 pins)
AVDD12: EVM Power (U6.9), ADC Power (C33.2 C34.2 FC2.3), ADC IO (6 pins)
AVDD18: EVM Power (U6.5), ADC Power (C47.2 C48.2 FC4.3), ADC IO (8 pins)
DVDD12: EVM Power (U6.8), ADC Power (C26.2 C27.2 FC1.3), ADC IO (C83.2 C84.2 U1.2 U1.47)
DVDD18: EVM Power (U6.4), ADC Power (C40.2 C41.2 FC3.3), ADC IO (C89.2 U1.58)
GND: EVM Power (35 pins), ADC Power DC-DC (33 pins), ADC Power (60 pins), LMH Power DC-DC (26 pins), LMH Power LDO (17 pins), ADC IO (30 pins), ADC Analog Input (15 pins), Amplifier (54 pins), FMC Sections 1-7  (96 pins), FMC Sections 8-14 (76 pins), FTDI USB Input (37 pins), Comms Level Shift (20 pins), I2C SPI Mux (10 pins)
MainPwr: EVM Power (9 pins), ADC Power DC-DC (8 pins), LMH Power DC-DC (C59.2 C60.2 R65.2 U17.18)
VADJ: FMC Sections 1-7  (J9.E39), FMC Sections 8-14 (J9.F40 J9.G39 J9.H40 R196.2), Comms Level Shift (8 pins)
ADC_RESET: ADC IO (U42.2), I2C SPI Mux (R250.1 R253.2 U33.10)
ADC_SCLK: ADC IO (U1.13), I2C SPI Mux (PP12.1 R251.2 U33.2)
ADC_SDIO: ADC IO (U1.36), I2C SPI Mux (PP14.1 R252.2 U33.7)
ADC_SEN: ADC IO (U1.14), I2C SPI Mux (PP13.1 R249.1 U33.5)
CHA_AMP_OUT_N: ADC Analog Input (C92.1), Amplifier (C135.2 L6.2)
CHA_AMP_OUT_P: ADC Analog Input (C101.2), Amplifier (C138.1 L8.2)
CHB_AMP_OUT_N: ADC Analog Input (C111.2), Amplifier (C154.2 L10.2)
CHB_AMP_OUT_P: ADC Analog Input (C120.1), Amplifier (C157.1 L12.2)
FMC_DCLK_n: ADC IO (R83.2), FMC Sections 8-14 (J9.G7)
FMC_DCLK_p: ADC IO (R82.2), FMC Sections 8-14 (J9.G6)
FMC_DOUT0_n: ADC IO (R85.2), FMC Sections 1-7  (J9.D9)
FMC_DOUT0_p: ADC IO (R84.2), FMC Sections 1-7  (J9.D8)
FMC_DOUT1_n: ADC IO (R87.2), FMC Sections 1-7  (J9.C19)
FMC_DOUT1_p: ADC IO (R86.2), FMC Sections 1-7  (J9.C18)
FMC_DOUT2_n: ADC IO (R89.2), FMC Sections 1-7  (J9.D18)
FMC_DOUT2_p: ADC IO (R88.2), FMC Sections 1-7  (J9.D17)
FMC_DOUT3_n: ADC IO (R91.2), FMC Sections 8-14 (J9.H20)
FMC_DOUT3_p: ADC IO (R90.2), FMC Sections 8-14 (J9.H19)
FMC_DOUT4_n: ADC IO (R93.2), FMC Sections 8-14 (J9.G19)
FMC_DOUT4_p: ADC IO (R92.2), FMC Sections 8-14 (J9.G18)
FMC_DOUT5_n: ADC IO (R95.2), FMC Sections 1-7  (J9.C15)
FMC_DOUT5_p: ADC IO (R94.2), FMC Sections 1-7  (J9.C14)
FMC_DOUT6_n: ADC IO (R97.2), FMC Sections 8-14 (J9.H17)
FMC_DOUT6_p: ADC IO (R96.2), FMC Sections 8-14 (J9.H16)
FMC_DOUT7_n: ADC IO (R99.2), FMC Sections 8-14 (J9.G16)
FMC_DOUT7_p: ADC IO (R98.2), FMC Sections 8-14 (J9.G15)
FMC_DOUT8_n: ADC IO (R101.2), FMC Sections 8-14 (J9.H14)
FMC_DOUT8_p: ADC IO (R100.2), FMC Sections 8-14 (J9.H13)
FMC_DOUT9_n: ADC IO (R103.2), FMC Sections 8-14 (J9.G13)
FMC_DOUT9_p: ADC IO (R102.2), FMC Sections 8-14 (J9.G12)
FMC_DOUT10_n: ADC IO (R105.2), FMC Sections 1-7  (J9.D15)
FMC_DOUT10_p: ADC IO (R104.2), FMC Sections 1-7  (J9.D14)
FMC_DOUT11_n: ADC IO (R107.2), FMC Sections 8-14 (J9.H11)
FMC_DOUT11_p: ADC IO (R106.2), FMC Sections 8-14 (J9.H10)
FMC_DOUT12_n: ADC IO (R109.2), FMC Sections 8-14 (J9.G10)
FMC_DOUT12_p: ADC IO (R108.2), FMC Sections 8-14 (J9.G9)
FMC_DOUT13_n: ADC IO (R115.2), FMC Sections 8-14 (J9.H8)
FMC_DOUT13_p: ADC IO (R114.2), FMC Sections 8-14 (J9.H7)
FMC_DOUT14_n: ADC IO (R118.2), FMC Sections 1-7  (J9.D12)
FMC_DOUT14_p: ADC IO (R117.2), FMC Sections 1-7  (J9.D11)
FMC_DOUT15_n: ADC IO (R120.2), FMC Sections 1-7  (J9.C11)
FMC_DOUT15_p: ADC IO (R119.2), FMC Sections 1-7  (J9.C10)
FMC_I2C_SCL: FMC Sections 1-7  (R180.1), I2C SPI Mux (U32.1)
FMC_I2C_SDA: FMC Sections 1-7  (R181.1), I2C SPI Mux (U32.7)
FMC_RESET: FMC Sections 8-14 (R193.1), Comms Level Shift (U34.4)
FMC_RESET_1p8V: Comms Level Shift (U34.9), I2C SPI Mux (U33.12)
FMC_SCLK: FMC Sections 8-14 (R200.1), Comms Level Shift (U34.1)
FMC_SCLK_1p8V: Comms Level Shift (U34.12), I2C SPI Mux (U33.16)
FMC_SDI_1p8V: FMC Sections 8-14 (R208.2), Comms Level Shift (NT2.1)
FMC_SDIO_1p8V: Comms Level Shift (NT2.2 R259.1 U34.10), I2C SPI Mux (U33.9)
FMC_SDO: FMC Sections 8-14 (R204.1), Comms Level Shift (U34.3)
FMC_SEN: FMC Sections 8-14 (R196.1 R199.1), Comms Level Shift (U34.2)
FMC_SEN_1p8V: Comms Level Shift (U34.11), I2C SPI Mux (U33.3)
FTDI_I2C_SCL: FTDI USB Input (R218.2), I2C SPI Mux (U32.2)
FTDI_I2C_SDA: FTDI USB Input (R220.2 R221.2), I2C SPI Mux (U32.6)
FTDI_RESET: FTDI USB Input (R222.2), Comms Level Shift (U36.4)
FTDI_RESET_1p8V: Comms Level Shift (U36.9), I2C SPI Mux (U33.11)
FTDI_SCLK: FTDI USB Input (R212.2 R216.2), Comms Level Shift (U36.1)
FTDI_SCLK_1p8V: Comms Level Shift (U36.12), I2C SPI Mux (U33.1)
FTDI_SDI_1p8V: FTDI USB Input (R211.2), Comms Level Shift (NT1.1)
FTDI_SDIO_1p8V: Comms Level Shift (NT1.2 R188.2 R266.1 U36.10), I2C SPI Mux (U33.8)
FTDI_SDO: FTDI USB Input (R214.2), Comms Level Shift (U36.3)
FTDI_SEN: FTDI USB Input (R209.1 R213.2), Comms Level Shift (U36.2)
FTDI_SEN_1p8V: Comms Level Shift (U36.11), I2C SPI Mux (U33.4)
GPIO0: ADC IO (R111.2), Comms Level Shift (U35.3)
GPIO0_DIR: FMC Sections 8-14 (R194.1), Comms Level Shift (R261.2 U35.11)
GPIO0_VADJ: FMC Sections 8-14 (R197.1), Comms Level Shift (U35.10)
GPIO1: ADC IO (R121.1), Comms Level Shift (U35.4)
GPIO1_DIR: FMC Sections 8-14 (R195.1), Comms Level Shift (R260.2 U35.12)
GPIO1_VADJ: FMC Sections 8-14 (R198.1), Comms Level Shift (U35.9)
ISENSE_AVDD12: EVM Power (U3.9), ADC Power (U10.4)
ISENSE_AVDD18: EVM Power (U3.5), ADC Power (U14.4)
ISENSE_DVDD12: EVM Power (U3.8), ADC Power (U8.4)
ISENSE_DVDD18: EVM Power (U3.4), ADC Power (U12.4)
PG-M2C: FMC Sections 1-7  (R183.2), FMC Sections 8-14 (J9.F1)
PwrGd_3p3Gen: EVM Power (R6.1 U5.7), ADC Power DC-DC (R14.1 R17.2 U7.24)
PwrGd_4p3V_LDO: LMH Power DC-DC (R64.1 U17.19), LMH Power LDO (R74.2)
PwrGd_Analog: ADC Power DC-DC (R13.1 U7.19), ADC Power (R63.1 U39.1)
PwrGd_AVDD18: EVM Power (Q1.1), ADC Power (R45.1 U15.4), LMH Power DC-DC (R60.1 U45.1)
SCL_I2C: EVM Power (U3.14 U6.14), FMC Sections 1-7  (U25.6), I2C SPI Mux (R245.1 TP5.1 U32.3)
SDA_I2C: EVM Power (U3.13 U6.13), FMC Sections 1-7  (U25.5), I2C SPI Mux (R246.1 TP6.1 U32.5)
Seq_1p2V: ADC Power DC-DC (R273.1 U19.6), ADC Power (R71.1 R110.1 U39.2 U43.2)
Seq_1p8V: ADC Power DC-DC (R274.1 U19.5), ADC Power (R76.1 R272.1 U40.2 U44.2)
Seq_LMH_Pwr: ADC Power DC-DC (R275.1 U19.4), LMH Power DC-DC (R77.1 U45.2)
VCM_AMP: ADC Analog Input (R139.2), Amplifier (C144.2 C163.2 U22.1 U24.1)

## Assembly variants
001: not fitted C57 C58 C67 C135 C136 C137 C138 C154 C155 C156 C157 D2 F1 Q1 R1 R14 R17 R22 R25 R26 R31 R34 R39 R42 R43 R48 R51 R58 R60 R63 R65 R69 R71 R72 R73 R75 R76 R77 R80 R81 R110 R111 R112 R113 R116 R121 R122 R123 R124 R127 R133 R134 R145 R147 R151 R152 R153 R164 R166 R170 R171 R172 R179 R184 R188 R189 R192 R247 R249 R250 R251 R252 R253 R255 R257 R258 R264 R272 TP1 TP3; alternate parts C101 -> RSMD020101699, C92 -> RSMD020101699, C120 -> RSMD020101699, C111 -> RSMD020101699, L7 -> RSMD020101699, L5 -> RSMD020101699, L8 -> RSMD020101699, L6 -> RSMD020101699, L9 -> RSMD020101699, L12 -> RSMD020101699, L11 -> RSMD020101699, L10 -> RSMD020101699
